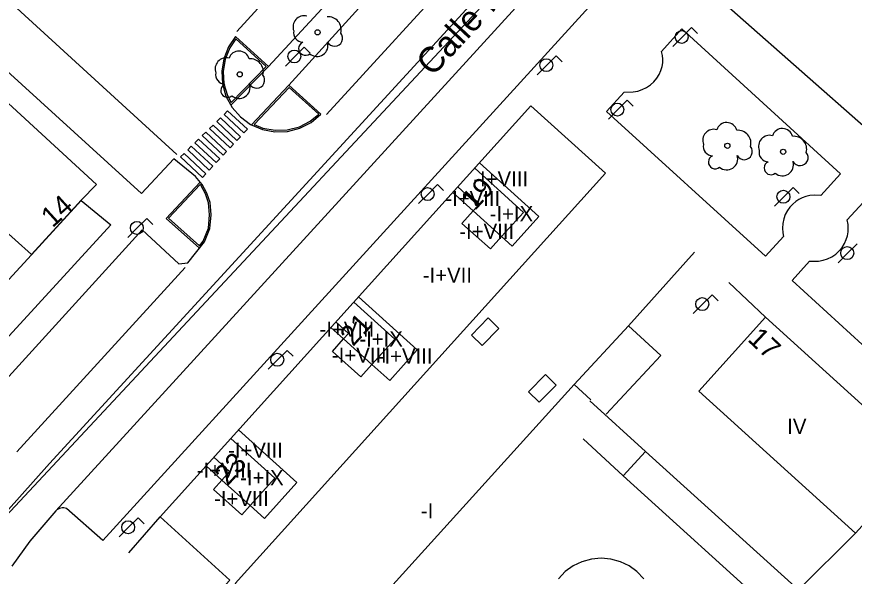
# Model space of a CAD drawing. Extents: x 282771 to 285132, y 4823109 to 4825496.
# Drawn here: x 283932.1 to 284014.7, y 4823334.3 to 4823389.4 of the extents above; entities that cross this region are included whole.
import ezdxf

# ---------------------------------------------------------------- set-up
doc = ezdxf.new("R2010")
doc.units = 0
for name, color, linetype in [('ACERA-BORDILLO', 7, 'Continuous'), ('ACERA-INTERIOR', 7, 'Continuous'), ('ARBOL', 7, 'Continuous'), ('BORDILLO', 7, 'Continuous'), ('CALLE-EJE', 7, 'Continuous'), ('CALLE-TEXTO', 7, 'Continuous'), ('EDIFICIO', 7, 'Continuous'), ('FAROLA', 7, 'Continuous'), ('MEDIANERA', 7, 'Continuous'), ('NUM-LOCAL', 7, 'Continuous'), ('NUM-PORTAL', 7, 'Continuous'), ('PASO-PEATONES', 7, 'Continuous'), ('SENAL-VIARIA', 7, 'Continuous'), ('TXT-ALTURA-EDIFICIO', 7, 'Continuous'), ('ZONA-VERDE', 7, 'Continuous')]:
    doc.layers.add(name, color=color, linetype=linetype)

msp = doc.modelspace()

# ---------------------------------------------------------------- linework, layer by layer
at = {"layer": 'ACERA-BORDILLO'}
for points in [[(284025.669, 4823431.16), (283940.55, 4823337.771), (283936.97, 4823340.921), (283936.83, 4823340.971), (283936.69, 4823340.991), (283936.55, 4823341.001), (283936.41, 4823340.981), (283936.27, 4823340.941), (283936.14, 4823340.881), (283936.02, 4823340.811), (283935.92, 4823340.721), (283933.35, 4823337.731), (283931.58, 4823335.261)], [(283927.283, 4823349.608), (283944.438, 4823368.404), (283948.058, 4823365.08), (283948.94, 4823365.148), (283950.594, 4823367.224), (283951.123, 4823368.539), (283951.245, 4823369.896), (283951.136, 4823371.103), (283950.811, 4823372.039), (283950.35, 4823372.894), (283949.686, 4823373.681), (283947.543, 4823375.417), (283944.37, 4823372.012), (283910.745, 4823402.619)]]:
    msp.add_lwpolyline(points, dxfattribs=at)
at = {"layer": 'ACERA-INTERIOR'}
for points in [[(283956.898, 4823384.528), (283953.181, 4823380.709)], [(283958.923, 4823382.678), (283955.226, 4823378.774)], [(283950.169, 4823373.108), (283946.811, 4823369.543), (283950.108, 4823366.613)], [(283998.95, 4823366.201), (283992.44, 4823358.961)], [(284002.31, 4823363.231), (284005.95, 4823359.791)], [(283979.64, 4823358.701), (283978.59, 4823359.741), (283976.93, 4823358.041), (283977.98, 4823357.011), (283979.64, 4823358.701)], [(283987.06, 4823353.171), (283992.44, 4823358.961)], [(283990.22, 4823350.241), (283995.6, 4823356.031), (283992.44, 4823358.961)], [(283985.28, 4823353.111), (283984.23, 4823354.151), (283982.57, 4823352.451), (283983.62, 4823351.421), (283985.28, 4823353.111)], [(283987.06, 4823353.171), (283965.41, 4823329.261), (283987.49, 4823309.122)], [(283988.7, 4823351.651), (283987.06, 4823353.171)], [(283994.095, 4823346.566), (283988.6, 4823351.541)], [(283991.91, 4823344.151), (283987.96, 4823347.821)], [(283994.095, 4823346.566), (283991.91, 4823344.151)], [(283994.1, 4823346.571), (283994.095, 4823346.566)], [(284009.19, 4823332.901), (283994.095, 4823346.566)], [(283991.91, 4823344.151), (284006.99, 4823330.481)], [(283943.12, 4823336.581), (283946.2, 4823340.121)], [(284014.82, 4823338.491), (284009.19, 4823332.901)], [(283993.93, 4823334.011), (283993.26, 4823334.711), (283992.48, 4823335.271), (283991.62, 4823335.691), (283990.69, 4823335.951), (283989.72, 4823336.041), (283988.76, 4823335.951)], [(283989.72, 4823336.041), (283989.73, 4823336.041)], [(283988.76, 4823335.951), (283987.83, 4823335.691), (283986.97, 4823335.271), (283986.19, 4823334.711), (283985.52, 4823334.011)]]:
    msp.add_lwpolyline(points, dxfattribs=at)
at = {"layer": 'ARBOL'}
for centre in [(283961.744, 4823387.893), (283954.06, 4823383.749), (284002.178, 4823376.701), (284007.678, 4823376.111)]:
    msp.add_circle(centre, 0.255, dxfattribs=at)
for centre, radius, start, end in [((283960.414, 4823388.423), 1.097, 75.4318, 200.55608), ((283962.804, 4823388.153), 1.272, 345.03273, 95.79925), ((283960.304, 4823387.853), 0.935, 168.59898, 268.13236), ((283963.414, 4823387.323), 0.797, 208.96246, 38.99103), ((283960.544, 4823386.303), 0.672, 113.73672, 309.4725), ((283961.684, 4823386.603), 1.086, 228.95447, 17.92796), ((283953.99, 4823385.009), 1.038, 15.64228, 161.38435), ((283952.73, 4823384.279), 1.097, 75.4318, 200.55608), ((283955.12, 4823384.009), 1.272, 345.03273, 95.79925), ((283952.62, 4823383.709), 0.935, 168.59898, 268.13236), ((283955.73, 4823383.179), 0.797, 208.96246, 38.99103), ((283952.86, 4823382.159), 0.672, 113.73672, 309.4725), ((283954, 4823382.459), 1.086, 228.95447, 17.92796), ((284002.108, 4823377.961), 1.038, 15.64228, 161.38435), ((284000.848, 4823377.231), 1.097, 75.4318, 200.55608), ((284003.238, 4823376.961), 1.272, 345.03273, 95.79925), ((284007.608, 4823377.371), 1.038, 15.64228, 161.38435), ((284006.348, 4823376.641), 1.097, 75.4318, 200.55608), ((284008.738, 4823376.371), 1.272, 345.03273, 95.79925), ((284000.738, 4823376.661), 0.935, 168.59898, 268.13236), ((284003.848, 4823376.131), 0.797, 208.96246, 38.99103), ((284000.978, 4823375.111), 0.672, 113.73672, 309.4725), ((284002.118, 4823375.411), 1.086, 228.95447, 17.92796), ((284006.238, 4823376.071), 0.935, 168.59898, 268.13236), ((284009.348, 4823375.541), 0.797, 208.96246, 38.99103), ((284006.478, 4823374.521), 0.672, 113.73672, 309.4725), ((284007.618, 4823374.821), 1.086, 228.95447, 17.92796)]:
    msp.add_arc(centre, radius, start, end, dxfattribs=at)
at = {"layer": 'BORDILLO'}
for points in [[(283985.355, 4823415.284), (283956.898, 4823384.528)], [(283956.898, 4823384.528), (283953.66, 4823387.491), (283952.94, 4823386.451), (283952.48, 4823385.291), (283952.28, 4823384.051), (283952.35, 4823382.801), (283952.7, 4823381.591), (283953.3, 4823380.491), (283954.13, 4823379.551), (283955.14, 4823378.811), (283956.3, 4823378.311), (283957.53, 4823378.081), (283958.78, 4823378.121), (283960, 4823378.441), (283961.11, 4823379.011), (283962.08, 4823379.821), (283958.923, 4823382.678), (283987.237, 4823413.843)]]:
    msp.add_lwpolyline(points, dxfattribs=at)
at = {"layer": 'CALLE-EJE'}
msp.add_lwpolyline([(284045.459, 4823466.67), (284021.402, 4823440.238), (284005.907, 4823420.439), (283918.081, 4823326.402)], dxfattribs=at)
at = {"layer": 'EDIFICIO'}
for points in [[(284033.189, 4823435.35), (284042.409, 4823426.931), (284013.53, 4823394.841), (284032.549, 4823377.401), (284051.039, 4823398.161), (284060.249, 4823389.661), (284034.909, 4823361.651), (283996.82, 4823395.211), (284029.549, 4823431.35), (284033.189, 4823435.35)], [(283933.52, 4823365.981), (283927.02, 4823371.771), (283920.03, 4823364.391), (283916.331, 4823367.761), (283909.861, 4823360.711), (283892.531, 4823376.621), (283905.791, 4823391.261), (283899.341, 4823397.111), (283905.881, 4823404.221), (283939.92, 4823372.901), (283938.43, 4823371.331), (283938.1, 4823370.981), (283933.52, 4823365.981)], [(283946.2, 4823340.121), (283982.8, 4823380.641), (283990.14, 4823374.001), (283953.6, 4823333.541), (283984.12, 4823305.462), (283977.73, 4823298.502), (283946.77, 4823327.001), (283947.1, 4823327.351), (283953.08, 4823333.871), (283946.2, 4823340.121)], [(283999.36, 4823352.521), (284005.95, 4823359.791), (284021.419, 4823345.761), (284014.82, 4823338.491), (283999.36, 4823352.521)]]:
    msp.add_lwpolyline(points, dxfattribs=at)
at = {"layer": 'FAROLA'}
for p, q in [((283998.654, 4823388.361), (283997.714, 4823387.431)), ((283999.244, 4823387.771), (283998.654, 4823388.361)), ((283997.714, 4823387.431), (283996.784, 4823386.491)), ((283960.432, 4823386.443), (283959.492, 4823385.513)), ((283961.022, 4823385.853), (283960.432, 4823386.443)), ((283985.293, 4823385.586), (283984.353, 4823384.656)), ((283985.883, 4823384.996), (283985.293, 4823385.586)), ((283959.492, 4823385.513), (283958.562, 4823384.573)), ((283984.353, 4823384.656), (283983.423, 4823383.716)), ((283992.306, 4823381.203), (283991.366, 4823380.273)), ((283992.896, 4823380.613), (283992.306, 4823381.203)), ((283991.366, 4823380.273), (283990.436, 4823379.333)), ((283973.584, 4823372.875), (283972.644, 4823371.945)), ((283974.174, 4823372.285), (283973.584, 4823372.875)), ((284008.687, 4823372.605), (284007.747, 4823371.675)), ((284009.277, 4823372.015), (284008.687, 4823372.605)), ((283972.644, 4823371.945), (283971.714, 4823371.005)), ((284007.747, 4823371.675), (284006.817, 4823370.735)), ((283944.89, 4823369.536), (283943.95, 4823368.606)), ((283945.48, 4823368.946), (283944.89, 4823369.536)), ((283943.95, 4823368.606), (283943.02, 4823367.666)), ((284014.988, 4823367.049), (284014.048, 4823366.119)), ((284014.048, 4823366.119), (284013.118, 4823365.179)), ((284000.68, 4823362.021), (283999.74, 4823361.091)), ((284001.27, 4823361.431), (284000.68, 4823362.021)), ((283999.74, 4823361.091), (283998.81, 4823360.151)), ((283958.744, 4823356.533), (283957.804, 4823355.603)), ((283959.334, 4823355.943), (283958.744, 4823356.533)), ((283957.804, 4823355.603), (283956.874, 4823354.663)), ((283944.031, 4823340.016), (283943.091, 4823339.086)), ((283944.621, 4823339.426), (283944.031, 4823340.016)), ((283943.091, 4823339.086), (283942.161, 4823338.146))]:
    msp.add_line(p, q, dxfattribs=at)
for centre, radius in [((283997.674, 4823387.431), 0.638), ((283959.452, 4823385.513), 0.637), ((283984.313, 4823384.656), 0.638), ((283991.326, 4823380.273), 0.638), ((283972.604, 4823371.945), 0.638), ((284007.707, 4823371.675), 0.638), ((283943.91, 4823368.606), 0.637), ((284014.008, 4823366.119), 0.638), ((283999.7, 4823361.091), 0.637), ((283957.764, 4823355.603), 0.638), ((283943.051, 4823339.086), 0.637)]:
    msp.add_circle(centre, radius, dxfattribs=at)
at = {"layer": 'MEDIANERA'}
for points in [[(283977.73, 4823375.021), (283983.57, 4823369.741), (283980.95, 4823366.821), (283979.9, 4823367.761)], [(283979.9, 4823367.761), (283982.06, 4823370.141), (283977.25, 4823374.491)], [(283975.59, 4823372.651), (283977.59, 4823370.831), (283977.1, 4823370.291)], [(283977.1, 4823370.291), (283975.1, 4823372.111)], [(283979.9, 4823367.761), (283978.8, 4823366.541), (283975.99, 4823369.051), (283977.1, 4823370.291)], [(283977.1, 4823370.291), (283979.9, 4823367.761)], [(283965.79, 4823361.801), (283971.58, 4823356.571), (283968.88, 4823353.551), (283967.11, 4823355.131)], [(283967.11, 4823355.131), (283969.36, 4823357.621), (283965.31, 4823361.271)], [(283963.55, 4823359.331), (283964.8, 4823358.201), (283964.31, 4823357.661)], [(283964.31, 4823357.661), (283963.06, 4823358.791)], [(283967.11, 4823355.131), (283966.01, 4823353.911), (283963.2, 4823356.421), (283964.31, 4823357.661)], [(283964.31, 4823357.661), (283967.11, 4823355.131)], [(283953.94, 4823348.691), (283959.69, 4823343.491), (283956.5, 4823339.961), (283955.1, 4823341.221)], [(283955.1, 4823341.221), (283957.54, 4823343.921), (283953.18, 4823347.851)], [(283951.51, 4823346.001), (283953.06, 4823344.591), (283952.29, 4823343.741)], [(283952.29, 4823343.741), (283950.74, 4823345.151)], [(283955.1, 4823341.221), (283954.27, 4823340.301), (283951.46, 4823342.811), (283952.29, 4823343.741)], [(283952.29, 4823343.741), (283955.1, 4823341.221)]]:
    msp.add_lwpolyline(points, dxfattribs=at)
at = {"layer": 'PASO-PEATONES'}
for points in [[(283952.868, 4823380.152), (283954.816, 4823378.335), (283954.475, 4823377.97), (283952.51, 4823379.802)], [(283952.152, 4823379.453), (283954.133, 4823377.604), (283953.792, 4823377.239), (283951.793, 4823379.103)], [(283951.435, 4823378.754), (283953.45, 4823376.874), (283953.109, 4823376.509), (283951.077, 4823378.404)], [(283951.743, 4823375.048), (283949.643, 4823377.006), (283950.002, 4823377.356), (283952.084, 4823375.413)], [(283952.426, 4823375.778), (283950.36, 4823377.705), (283950.718, 4823378.055), (283952.767, 4823376.143)], [(283951.06, 4823374.317), (283948.927, 4823376.307), (283949.285, 4823376.657), (283951.402, 4823374.682)], [(283950.377, 4823373.587), (283948.21, 4823375.608), (283948.569, 4823375.957), (283950.719, 4823373.952)]]:
    msp.add_lwpolyline(points, close=True, dxfattribs=at)
at = {"layer": 'SENAL-VIARIA'}
for points in [[(283935.92, 4823340.721), (284023.186, 4823436.153)], [(283981.73, 4823418.573), (283953.767, 4823387.96)], [(283990.581, 4823410.334), (283962.621, 4823379.799)], [(283914.331, 4823406.491), (283947.87, 4823375.851)], [(283930.982, 4823340.538), (283935.294, 4823345.359), (283989.244, 4823404.159)], [(283948.676, 4823364.709), (283932.073, 4823346.51)]]:
    msp.add_lwpolyline(points, dxfattribs=at)
at = {"layer": 'ZONA-VERDE'}
for p, q in [((283995.665, 4823386.012), (283997.686, 4823388.229)), ((283997.686, 4823388.229), (284013.345, 4823373.948)), ((283995.792, 4823385.596), (283995.665, 4823386.012)), ((283995.822, 4823385.263), (283995.792, 4823385.596)), ((283995.736, 4823384.521), (283995.801, 4823384.9)), ((283995.801, 4823384.9), (283995.822, 4823385.263)), ((283953.203, 4823380.983), (283956.675, 4823384.529)), ((283995.446, 4823383.745), (283995.619, 4823384.133)), ((283995.619, 4823384.133), (283995.736, 4823384.521)), ((283994.925, 4823383.02), (283995.215, 4823383.37)), ((283995.215, 4823383.37), (283995.446, 4823383.745)), ((283958.952, 4823382.449), (283955.471, 4823378.796)), ((283993.773, 4823382.24), (283994.195, 4823382.445)), ((283994.195, 4823382.445), (283994.583, 4823382.707)), ((283994.583, 4823382.707), (283994.925, 4823383.02)), ((283990.267, 4823380.093), (283992.004, 4823381.998)), ((283992.004, 4823381.998), (283992.883, 4823382.024)), ((283992.883, 4823382.024), (283993.331, 4823382.1)), ((283993.331, 4823382.1), (283993.773, 4823382.24)), ((284005.926, 4823365.813), (283990.267, 4823380.093)), ((284013.345, 4823373.948), (284011.396, 4823371.811)), ((284009.558, 4823371.561), (284009.234, 4823371.397)), ((284009.919, 4823371.694), (284009.558, 4823371.561)), ((284010.314, 4823371.787), (284009.919, 4823371.694)), ((284010.736, 4823371.83), (284010.314, 4823371.787)), ((284011.396, 4823371.811), (284010.736, 4823371.83)), ((284014.017, 4823369.393), (284015.98, 4823371.545)), ((283933.509, 4823365.961), (283938.089, 4823370.961)), ((283938.089, 4823370.961), (283938.419, 4823371.311)), ((283938.419, 4823371.311), (283941.339, 4823368.901)), ((284008.635, 4823370.952), (284008.357, 4823370.657)), ((284008.93, 4823371.198), (284008.635, 4823370.952)), ((284009.234, 4823371.397), (284008.93, 4823371.198)), ((284007.899, 4823369.925), (284007.74, 4823369.499)), ((284008.108, 4823370.313), (284007.899, 4823369.925)), ((284008.357, 4823370.657), (284008.108, 4823370.313)), ((284007.641, 4823369.046), (284007.607, 4823368.579)), ((284007.74, 4823369.499), (284007.641, 4823369.046)), ((284014.095, 4823368.941), (284014.017, 4823369.393)), ((283941.339, 4823368.901), (283930.589, 4823357.161)), ((284007.607, 4823368.579), (284007.641, 4823368.112)), ((284014.029, 4823367.837), (284014.095, 4823368.217)), ((284014.115, 4823368.579), (284014.095, 4823368.941)), ((284014.095, 4823368.217), (284014.115, 4823368.579)), ((284007.715, 4823367.775), (284005.926, 4823365.813)), ((284007.641, 4823368.112), (284007.715, 4823367.775)), ((284013.74, 4823367.062), (284013.913, 4823367.449)), ((284013.913, 4823367.449), (284014.029, 4823367.837)), ((283950.089, 4823366.83), (283950.463, 4823367.3)), ((284013.219, 4823366.336), (284013.508, 4823366.686)), ((284013.508, 4823366.686), (284013.74, 4823367.062)), ((283927.72, 4823359.68), (283933.509, 4823365.961)), ((284012.067, 4823365.557), (284012.488, 4823365.761)), ((284012.488, 4823365.761), (284012.876, 4823366.024)), ((284012.876, 4823366.024), (284013.219, 4823366.336)), ((284008.56, 4823363.41), (284010.297, 4823365.315)), ((284010.297, 4823365.315), (284011.177, 4823365.34)), ((284011.177, 4823365.34), (284011.625, 4823365.416)), ((284011.625, 4823365.416), (284012.067, 4823365.557)), ((284023.399, 4823349.877), (284008.56, 4823363.41))]:
    msp.add_line(p, q, dxfattribs=at)
for points in [[(283956.675, 4823384.529), (283953.686, 4823387.264), (283953.073, 4823386.38), (283952.626, 4823385.251), (283952.431, 4823384.043), (283952.499, 4823382.826), (283952.84, 4823381.648), (283953.203, 4823380.983)], [(283955.471, 4823378.796), (283956.344, 4823378.455), (283957.542, 4823378.231), (283958.758, 4823378.27), (283959.946, 4823378.582), (283961.027, 4823379.137), (283961.851, 4823379.825), (283958.952, 4823382.449)], [(283950.163, 4823372.883), (283947.026, 4823369.553), (283950.089, 4823366.83)], [(283950.463, 4823367.3), (283950.975, 4823368.575), (283951.094, 4823369.896), (283950.989, 4823371.072), (283950.673, 4823371.979), (283950.225, 4823372.809), (283950.163, 4823372.883)]]:
    msp.add_lwpolyline(points, dxfattribs=at)

# ---------------------------------------------------------------- texts
at = {"layer": 'CALLE-TEXTO'}
msp.add_text('Calle Puerto de Ventana', height=2.5, rotation=46.9559, dxfattribs=at).set_placement((283973.077, 4823383.456))
at = {"layer": 'NUM-LOCAL'}
msp.add_text('14', height=2, rotation=42.20431, dxfattribs=at).set_placement((283935.582, 4823368.557))
at = {"layer": 'NUM-PORTAL'}
for s, rotation, p in [('19', 47.70004, (283977.271, 4823370.253)), ('21', 47.70004, (283965.246, 4823356.849)), ('17', 316.71004, (284004.084, 4823357.531)), ('23', 47.70004, (283952.872, 4823343.114))]:
    msp.add_text(s, height=2, rotation=rotation, dxfattribs=at).set_placement(p)
at = {"layer": 'TXT-ALTURA-EDIFICIO'}
for s, p in [('-I+VIII', (283977.107, 4823372.691)), ('-I+VIII', (283974.347, 4823370.761)), ('-I+IX', (283978.721, 4823369.251)), ('-I+VIII', (283975.727, 4823367.521)), ('-I+VII', (283972.128, 4823363.201)), ('-I+VIII', (283961.937, 4823357.871)), ('-I+IX', (283965.861, 4823356.911)), ('-I+VIII', (283963.157, 4823355.311)), ('-I+VIII', (283967.677, 4823355.221)), ('IV', (284008.09, 4823348.281)), ('-I+VIII', (283952.907, 4823345.941)), ('-I+VIII', (283949.817, 4823343.961)), ('-I+IX', (283954.101, 4823343.231)), ('-I+VIII', (283951.527, 4823341.171)), ('-I', (283971.936, 4823339.951))]:
    msp.add_text(s, height=1.5, rotation=0.00004, dxfattribs=at).set_placement(p)

doc.saveas('drawing.dxf')
